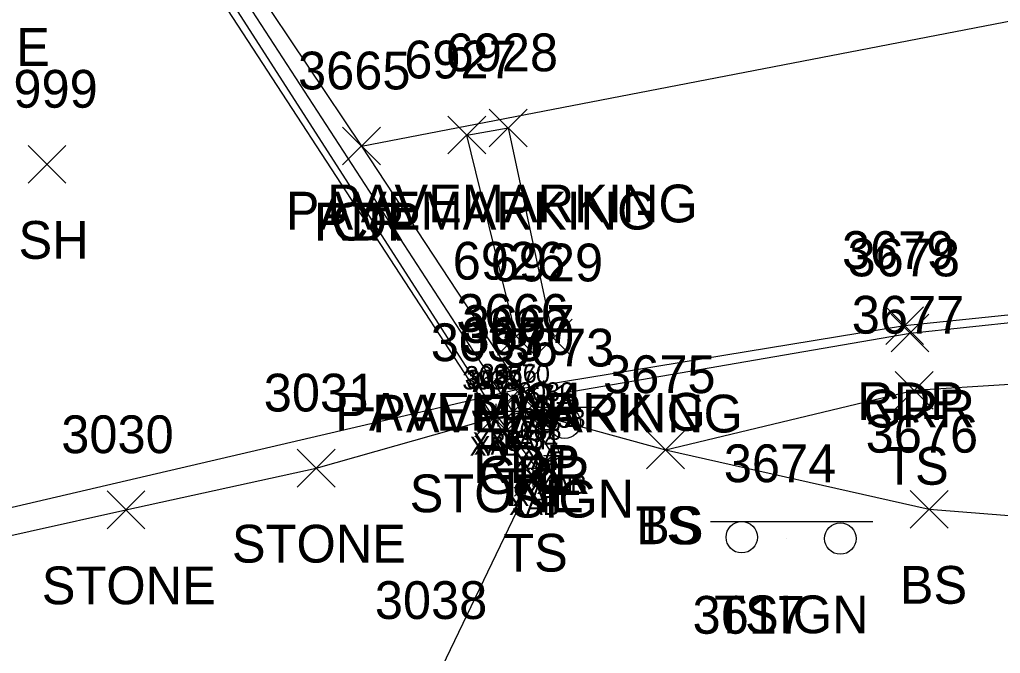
# Model space of a CAD drawing. Extents: x 1505656 to 1508446, y 700805 to 703031.
# Drawn here: x 1506524.5 to 1506576.4, y 701784.4 to 701818 of the extents above; entities that cross this region are included whole.
import ezdxf

# ---------------------------------------------------------------- set-up
doc = ezdxf.new("R2010")
doc.units = 0
for name, color, linetype in [('B_A', 7, 'Continuous'), ('B_I', 7, 'Continuous'), ('B_TIC', 7, 'Continuous'), ('BELB', 7, 'Continuous'), ('BSE', 7, 'Continuous'), ('BSUBM', 7, 'Continuous'), ('L_A', 7, 'Continuous'), ('L_I', 7, 'Continuous'), ('L_TIC', 7, 'Continuous'), ('LASF', 7, 'Continuous'), ('LELB', 7, 'Continuous'), ('P_A', 7, 'Continuous'), ('P_I', 7, 'Continuous'), ('P_TIC', 7, 'Continuous'), ('PET', 7, 'Continuous'), ('PRC', 7, 'Continuous'), ('R_A', 7, 'Continuous'), ('R_I', 7, 'Continuous'), ('R_TIC', 7, 'Continuous'), ('RGR', 7, 'Continuous'), ('S_A', 7, 'Continuous'), ('S_I', 7, 'Continuous'), ('S_TIC', 7, 'Continuous'), ('SSGN', 7, 'Continuous'), ('STS', 7, 'Continuous')]:
    doc.layers.add(name, color=color, linetype=linetype)

msp = doc.modelspace()

# ---------------------------------------------------------------- linework, layer by layer
at = {"layer": 'B_TIC'}
for p, q in [((1506549.704, 701797.111), (1506549.779, 701797.111)), ((1506550.564, 701797.232), (1506550.64, 701797.232)), ((1506550.564, 701797.232), (1506550.64, 701797.232)), ((1506551.262, 701797.199), (1506551.338, 701797.199)), ((1506549.574, 701796.872), (1506549.649, 701796.872)), ((1506549.803, 701796.914), (1506549.878, 701796.914)), ((1506551.928, 701796.101), (1506552.003, 701796.101)), ((1506552.509, 701796.25), (1506552.585, 701796.25)), ((1506552.694, 701794.884), (1506552.77, 701794.884)), ((1506552.694, 701794.884), (1506552.77, 701794.884)), ((1506553.114, 701794.844), (1506553.19, 701794.844)), ((1506551.854, 701794.202), (1506551.929, 701794.202)), ((1506551.854, 701794.202), (1506551.929, 701794.202)), ((1506551.658, 701793.729), (1506551.734, 701793.729))]:
    msp.add_line(p, q, dxfattribs=at)
for points in [[(1506549.7, 701796.611), (1506549.7, 701797.611)], [(1506550.561, 701796.732), (1506550.561, 701797.732)], [(1506550.561, 701796.732), (1506550.561, 701797.732)], [(1506551.259, 701796.699), (1506551.259, 701797.699)], [(1506549.2, 701797.111), (1506550.2, 701797.111)], [(1506549.57, 701796.372), (1506549.57, 701797.372)], [(1506549.799, 701796.414), (1506549.799, 701797.414)], [(1506550.061, 701797.232), (1506551.061, 701797.232)], [(1506550.061, 701797.232), (1506551.061, 701797.232)], [(1506550.759, 701797.199), (1506551.759, 701797.199)], [(1506549.07, 701796.872), (1506550.07, 701796.872)], [(1506549.299, 701796.914), (1506550.299, 701796.914)], [(1506551.924, 701795.601), (1506551.924, 701796.601)], [(1506552.506, 701795.75), (1506552.506, 701796.75)], [(1506551.424, 701796.101), (1506552.424, 701796.101)], [(1506552.006, 701796.25), (1506553.006, 701796.25)], [(1506552.691, 701794.384), (1506552.691, 701795.384)], [(1506552.691, 701794.384), (1506552.691, 701795.384)], [(1506553.111, 701794.344), (1506553.111, 701795.344)], [(1506551.85, 701793.702), (1506551.85, 701794.702)], [(1506551.85, 701793.702), (1506551.85, 701794.702)], [(1506552.191, 701794.884), (1506553.191, 701794.884)], [(1506552.191, 701794.884), (1506553.191, 701794.884)], [(1506552.611, 701794.844), (1506553.611, 701794.844)], [(1506551.35, 701794.202), (1506552.35, 701794.202)], [(1506551.35, 701794.202), (1506552.35, 701794.202)], [(1506551.655, 701793.229), (1506551.655, 701794.229)], [(1506551.155, 701793.729), (1506552.155, 701793.729)]]:
    msp.add_lwpolyline(points, dxfattribs=at)
at = {"layer": 'BELB'}
msp.add_lwpolyline([(1506513.703, 701789.722), (1506550.994, 701798.425)], dxfattribs=at)
at = {"layer": 'BSE'}
for points in [[(1506550.561, 701797.232), (1506549.7, 701797.111), (1506532.032, 701824.61), (1506532.672, 701824.779)], [(1506550.561, 701797.232), (1506532.672, 701824.779)]]:
    msp.add_lwpolyline(points, dxfattribs=at)
at = {"layer": 'BSUBM'}
for points in [[(1506552.506, 701796.25), (1506553.111, 701794.844), (1506551.655, 701793.729), (1506549.57, 701796.872), (1506530.033, 701826.863)], [(1506551.85, 701794.202), (1506549.799, 701796.914), (1506551.259, 701797.199), (1506551.924, 701796.101), (1506552.691, 701794.884)], [(1506551.85, 701794.202), (1506552.691, 701794.884)]]:
    msp.add_lwpolyline(points, dxfattribs=at)
at = {"layer": 'L_TIC'}
for points in [[(1506524.925, 701809.291), (1506526.925, 701811.291)], [(1506526.925, 701809.291), (1506524.925, 701811.291)], [(1506570.814, 701797.329), (1506572.814, 701799.329)], [(1506572.814, 701797.329), (1506570.814, 701799.329)], [(1506550.259, 701796.199), (1506552.259, 701798.199)], [(1506552.259, 701796.199), (1506550.259, 701798.199)], [(1506548.57, 701795.872), (1506550.57, 701797.872)], [(1506550.57, 701795.872), (1506548.57, 701797.872)], [(1506557.655, 701794.179), (1506559.655, 701796.179)], [(1506559.655, 701794.179), (1506557.655, 701796.179)], [(1506557.655, 701794.179), (1506559.655, 701796.179)], [(1506559.655, 701794.179), (1506557.655, 701796.179)], [(1506539.163, 701793.207), (1506541.163, 701795.207)], [(1506541.163, 701793.207), (1506539.163, 701795.207)], [(1506550.655, 701792.729), (1506552.655, 701794.729)], [(1506552.655, 701792.729), (1506550.655, 701794.729)], [(1506529.102, 701791), (1506531.102, 701793)], [(1506531.102, 701791), (1506529.102, 701793)], [(1506571.608, 701791.028), (1506573.608, 701793.028)], [(1506573.608, 701791.028), (1506571.608, 701793.028)]]:
    msp.add_lwpolyline(points, dxfattribs=at)
at = {"layer": 'LASF'}
msp.add_lwpolyline([(1506497.97, 701814.904), (1506500.687, 701813.308), (1506502.637, 701809.994), (1506506.972, 701803.588), (1506509.112, 701800.303), (1506510.827, 701794.15), (1506514.895, 701788.609), (1506530.102, 701792), (1506540.163, 701794.207), (1506549.57, 701796.872)], dxfattribs=at)
at = {"layer": 'LELB'}
for points in [[(1506551.259, 701797.199), (1506558.655, 701795.179), (1506571.814, 701798.329), (1506587.005, 701799.292), (1506612.691, 701800.384), (1506643.097, 701803.075), (1506686.408, 701805.31), (1506719.431, 701803.507), (1506758.517, 701801.606), (1506800.37, 701797.227), (1506837.502, 701789.661)], [(1506558.655, 701795.179), (1506572.608, 701792.028), (1506586.383, 701790.939), (1506613.464, 701792.005), (1506645.102, 701792.548), (1506687.221, 701796.522), (1506721.339, 701793.211), (1506758.892, 701789.886), (1506799.477, 701793.759), (1506835.546, 701784.174), (1506872.573, 701779.991)], [(1506551.655, 701793.729), (1506546.611, 701783.221), (1506540.769, 701773.441), (1506532.97, 701760.486)]]:
    msp.add_lwpolyline(points, dxfattribs=at)
at = {"layer": 'P_TIC'}
for points in [[(1506541.563, 701810.258), (1506543.563, 701812.258)], [(1506543.563, 701810.258), (1506541.563, 701812.258)], [(1506541.563, 701810.258), (1506543.563, 701812.258)], [(1506543.563, 701810.258), (1506541.563, 701812.258)], [(1506570.308, 701800.753), (1506572.308, 701802.753)], [(1506572.308, 701800.753), (1506570.308, 701802.753)], [(1506549.994, 701797.425), (1506551.994, 701799.425)], [(1506551.994, 701797.425), (1506549.994, 701799.425)]]:
    msp.add_lwpolyline(points, dxfattribs=at)
at = {"layer": 'PET'}
msp.add_lwpolyline([(1506503.963, 701935.538), (1506531.718, 701909.612), (1506554.951, 701887), (1506562.539, 701879.069), (1506567.48, 701868.844), (1506568.908, 701854.511), (1506562.935, 701840.149), (1506555.323, 701831.938), (1506552.833, 701829.172), (1506534.041, 701823.974), (1506542.563, 701811.258), (1506550.994, 701798.425), (1506571.308, 701801.753), (1506587.173, 701803.395), (1506614.433, 701806.451), (1506642.201, 701807.517), (1506684.835, 701809.296), (1506720.174, 701808.917), (1506758.847, 701806.498), (1506801.05, 701801.395), (1506837.914, 701794.781)], dxfattribs=at)
at = {"layer": 'PRC'}
msp.add_lwpolyline([(1506542.563, 701811.258), (1506583.456, 701819.163), (1506611.915, 701823.044), (1506639.632, 701825.584), (1506682.361, 701827.381), (1506720.712, 701826.613), (1506759.113, 701825.094), (1506802.873, 701820.093), (1506841.694, 701813.277), (1506883.623, 701802.647), (1506939.518, 701784.018), (1506961.706, 701775.319), (1506990.861, 701762.611), (1507014.943, 701750.701), (1507047.18, 701733.313), (1507059.635, 701726.12), (1507093.714, 701705.344), (1507109.291, 701695.301), (1507149.331, 701669.456), (1507158.784, 701662.649), (1507185.012, 701645.13), (1507221.624, 701620.548), (1507265.062, 701591.23)], dxfattribs=at)
at = {"layer": 'R_TIC'}
for points in [[(1506570.594, 701800.361), (1506572.594, 701802.361)], [(1506572.594, 701800.361), (1506570.594, 701802.361)], [(1506550.24, 701796.839), (1506552.24, 701798.839)], [(1506552.24, 701796.839), (1506550.24, 701798.839)]]:
    msp.add_lwpolyline(points, dxfattribs=at)
at = {"layer": 'RGR'}
msp.add_lwpolyline([(1506551.24, 701797.839), (1506571.594, 701801.361), (1506614.429, 701805.89), (1506642.246, 701806.936), (1506685.176, 701808.53), (1506719.99, 701808.29), (1506758.763, 701805.832), (1506800.88, 701800.842), (1506837.733, 701793.829), (1506878.725, 701783.931), (1506932.115, 701767.5), (1506956.302, 701757.767), (1506981.816, 701746.54), (1507005.678, 701734.484), (1507036.84, 701717.623), (1507049.284, 701710.579), (1507081.069, 701691.673), (1507098.391, 701680.194), (1507136.763, 701655.283), (1507148.635, 701647.399), (1507175.486, 701629.55), (1507209.72, 701606.655), (1507254.701, 701574.394), (1507264.029, 701565.842)], dxfattribs=at)
at = {"layer": 'S_TIC'}
for points in [[(1506549.324, 701811.218), (1506551.324, 701813.218)], [(1506551.324, 701811.218), (1506549.324, 701813.218)], [(1506547.136, 701810.84), (1506549.136, 701812.84)], [(1506549.136, 701810.84), (1506547.136, 701812.84)], [(1506549.755, 701800.188), (1506551.755, 701802.188)], [(1506551.755, 701800.188), (1506549.755, 701802.188)], [(1506551.715, 701800.095), (1506553.715, 701802.095)], [(1506553.715, 701800.095), (1506551.715, 701802.095)]]:
    msp.add_lwpolyline(points, dxfattribs=at)
at = {"layer": 'SSGN'}
for p, q in [((1506551.671, 701797.443), (1506555.005, 701797.443)), ((1506553.318, 701796.61), (1506553.318, 701796.61)), ((1506561.028, 701791.386), (1506569.625, 701791.386)), ((1506565.05, 701790.482), (1506565.05, 701790.482))]:
    msp.add_line(p, q, dxfattribs=at)
for centre in [(1506553.318, 701796.61), (1506562.689, 701790.552), (1506567.904, 701790.482)]:
    msp.add_circle(centre, 0.833, dxfattribs=at)
at = {"layer": 'STS'}
msp.add_lwpolyline([(1506550.755, 701801.188), (1506548.136, 701811.84), (1506550.324, 701812.218), (1506552.715, 701801.095)], dxfattribs=at)

# ---------------------------------------------------------------- texts
at = {"layer": 'B_A'}
for s, p in [('XBS', (1506548.44, 701795.111)), ('XBS', (1506549.301, 701795.232)), ('XBS', (1506549.301, 701795.232)), ('XAT', (1506549.963, 701795.199)), ('XAB', (1506548.291, 701794.872)), ('XAT', (1506548.504, 701794.914)), ('XAT', (1506550.629, 701794.101)), ('XAB', (1506551.226, 701794.25)), ('XAT', (1506551.396, 701792.884)), ('XAT', (1506551.396, 701792.884)), ('XAB', (1506551.831, 701792.844)), ('XAT', (1506550.555, 701792.202)), ('XAT', (1506550.555, 701792.202)), ('XAB', (1506550.375, 701791.729))]:
    msp.add_text(s, height=1, dxfattribs=at).set_placement(p)
at = {"layer": 'B_I'}
for s, p in [('3036', (1506548.864, 701798.732)), ('3036', (1506548.864, 701798.732)), ('3670', (1506549.562, 701798.699)), ('3035', (1506547.901, 701798.372)), ('3037', (1506548.031, 701798.611)), ('3669', (1506548.118, 701798.414)), ('3032', (1506550.837, 701797.75)), ('3671', (1506550.554, 701797.601)), ('3672', (1506551.037, 701796.384)), ('3672', (1506551.037, 701796.384)), ('3033', (1506551.442, 701796.344)), ('3668', (1506550.173, 701795.702)), ('3668', (1506550.173, 701795.702)), ('3034', (1506549.985, 701795.229))]:
    msp.add_text(s, height=1, dxfattribs=at).set_placement(p)
at = {"layer": 'L_A'}
for s, p in [('STONE', (1506516.858, 701815.502)), ('SH', (1506524.414, 701805.291)), ('TS', (1506570.223, 701793.329)), ('TS', (1506549.668, 701792.199)), ('STONE', (1506545.114, 701791.872)), ('TS', (1506557.064, 701790.179)), ('BS', (1506557.096, 701790.179)), ('STONE', (1506535.707, 701789.207)), ('TS', (1506550.064, 701788.729)), ('STONE', (1506525.645, 701787)), ('BS', (1506571.049, 701787.028))]:
    msp.add_text(s, height=2, dxfattribs=at).set_placement(p)
at = {"layer": 'L_I'}
for s, p in [('2999', (1506522.658, 701813.291)), ('3677', (1506568.507, 701801.329)), ('3035', (1506546.232, 701799.872)), ('3670', (1506547.865, 701800.199)), ('3675', (1506555.348, 701798.179)), ('3675', (1506555.348, 701798.179)), ('3031', (1506537.392, 701797.207)), ('3034', (1506548.316, 701796.729)), ('3030', (1506526.677, 701795)), ('3676', (1506569.246, 701795.028)), ('3038', (1506543.272, 701786.221)), ('3617', (1506560.085, 701785.44))]:
    msp.add_text(s, height=2, dxfattribs=at).set_placement(p)
at = {"layer": 'P_A'}
for s, p in [('RDP', (1506540.051, 701806.258)), ('CR', (1506540.996, 701806.258)), ('RDP', (1506568.797, 701796.753)), ('RDP', (1506548.482, 701793.425))]:
    msp.add_text(s, height=2, dxfattribs=at).set_placement(p)
at = {"layer": 'P_I'}
for s, p in [('3665', (1506539.208, 701814.258)), ('3665', (1506539.208, 701814.258)), ('3679', (1506567.993, 701804.753)), ('3666', (1506547.584, 701801.425))]:
    msp.add_text(s, height=2, dxfattribs=at).set_placement(p)
at = {"layer": 'R_A'}
for p in [(1506569.082, 701796.361), (1506548.728, 701792.839)]:
    msp.add_text('GRR', height=2, dxfattribs=at).set_placement(p)
at = {"layer": 'R_I'}
for s, p in [('3678', (1506568.286, 701804.361)), ('3667', (1506547.885, 701800.839))]:
    msp.add_text(s, height=2, dxfattribs=at).set_placement(p)
at = {"layer": 'S_A'}
for s, p in [('PAVEMARKING', (1506540.741, 701807.218)), ('PAVEMARKING', (1506538.554, 701806.84)), ('PAVEMARKING', (1506541.173, 701796.188)), ('PAVEMARKING', (1506543.132, 701796.095)), ('SIGN', (1506550.456, 701791.589)), ('TSIGN', (1506561.226, 701785.464))]:
    msp.add_text(s, height=2, dxfattribs=at).set_placement(p)
at = {"layer": 'S_I'}
for s, p in [('6927', (1506544.829, 701814.84)), ('6928', (1506547.017, 701815.218)), ('6926', (1506547.393, 701804.188)), ('6929', (1506549.4, 701804.095)), ('3673', (1506549.991, 701799.589)), ('3674', (1506561.737, 701793.464))]:
    msp.add_text(s, height=2, dxfattribs=at).set_placement(p)

doc.saveas('drawing.dxf')
